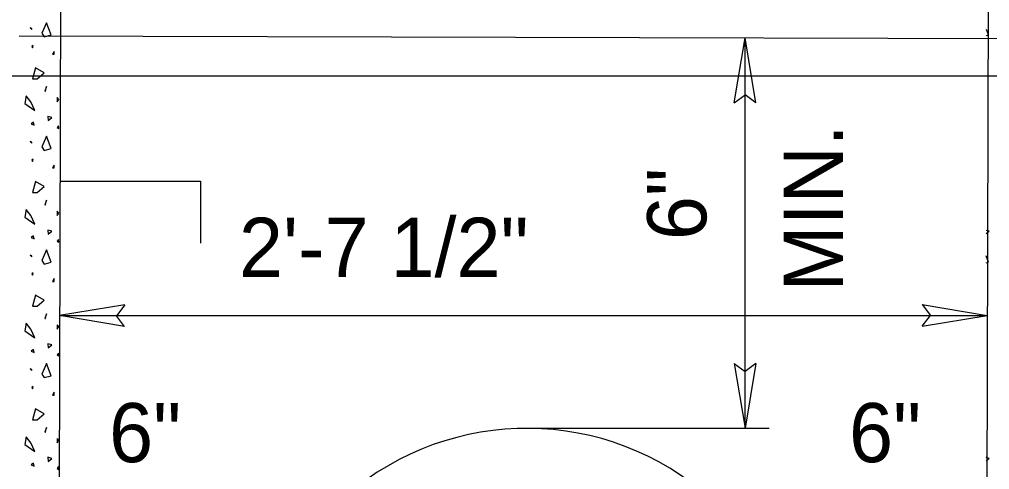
# Model space of a CAD drawing. Extents: x 9.6 to 16.8, y 2.2 to 12.2.
# Drawn here: x 14.996 to 15.979, y 7.746 to 8.202 of the extents above; entities that cross this region are included whole.
import ezdxf

# ---------------------------------------------------------------- set-up
doc = ezdxf.new("R2010")
doc.units = 0
for name, color, linetype in [('DETL-DIMS', 7, 'Continuous'), ('DETL-LINE', 7, 'Continuous'), ('DETL-NOTE', 7, 'Continuous'), ('DETL-PATT', 7, 'Continuous')]:
    doc.layers.add(name, color=color, linetype=linetype)

msp = doc.modelspace()

# ---------------------------------------------------------------- linework, layer by layer
at = {"layer": 'DETL-DIMS'}
for p, q in [((15.72059, 8.11769), (15.73157, 8.18357)), ((15.74255, 8.11769), (15.73157, 8.18357)), ((15.73157, 7.78769), (15.73157, 8.18357)), ((15.72059, 8.11769), (15.73157, 8.12592)), ((15.74255, 8.11769), (15.73157, 8.12592)), ((15.10275, 7.91282), (15.03682, 7.90196)), ((15.10275, 7.91282), (15.09447, 7.90184)), ((15.91118, 7.91306), (15.97702, 7.90196)), ((15.91118, 7.91306), (15.91937, 7.90208)), ((15.10267, 7.89086), (15.03682, 7.90196)), ((15.03682, 7.90196), (15.97702, 7.90196)), ((15.10267, 7.89086), (15.09447, 7.90184)), ((15.9111, 7.8911), (15.91937, 7.90208)), ((15.9111, 7.8911), (15.97702, 7.90196)), ((15.72059, 7.85357), (15.73157, 7.78769)), ((15.72059, 7.85357), (15.73157, 7.84533)), ((15.74255, 7.85357), (15.73157, 7.78769)), ((15.74255, 7.85357), (15.73157, 7.84533)), ((15.51027, 7.78769), (15.75604, 7.78769))]:
    msp.add_line(p, q, dxfattribs=at)
at = {"layer": 'DETL-LINE'}
for p, q in [((15.03902, 8.74647), (15.03486, 7.16059)), ((15.9791, 8.70102), (15.97506, 7.16059)), ((14.99573, 8.18549), (16.02733, 8.18278)), ((14.97361, 8.14518), (16.04459, 8.14518)), ((15.03804, 8.03835), (15.17957, 8.03835)), ((15.17957, 8.03835), (15.17957, 7.97545))]:
    msp.add_line(p, q, dxfattribs=at)
msp.add_arc((15.51033, 7.50778), 0.27991, 325.61931, 213.35871, dxfattribs=at)
at = {"layer": 'DETL-PATT'}
for points in [[(15.00871, 8.19298), (15.00698, 8.19357), (15.00871, 8.19184)], [(15.02125, 8.18467), (15.02831, 8.18651), (15.02353, 8.1989), (15.01886, 8.18831)], [(15.00996, 8.17576), (15.00871, 8.17463), (15.00941, 8.17337)], [(15.03129, 8.16984), (15.02957, 8.16686), (15.03129, 8.16686)], [(15.01404, 8.14188), (15.02125, 8.14796), (15.01235, 8.15318), (15.00941, 8.14188)], [(15.0218, 8.12945), (15.02239, 8.12945), (15.02353, 8.13427)], [(15.00275, 8.12467), (15.00165, 8.11702), (15.01165, 8.10984), (15.00757, 8.11875)], [(15.03424, 8.12298), (15.03424, 8.11875), (15.03608, 8.12114)], [(15.02478, 8.10392), (15.02533, 8.0998), (15.02886, 8.10278)], [(15.00812, 8.09627), (15.0111, 8.09502), (15.01051, 8.09796)], [(15.03424, 8.09263), (15.03608, 8.09149), (15.03553, 8.09443)], [(15.02125, 8.06945), (15.02831, 8.07129), (15.02353, 8.08373), (15.01886, 8.07314)], [(15.00871, 8.0778), (15.00698, 8.07835), (15.00871, 8.07667)], [(15.00996, 8.06055), (15.00871, 8.05945), (15.00941, 8.05816)], [(15.03129, 8.05463), (15.02957, 8.05169), (15.03129, 8.05169)], [(15.01404, 8.02667), (15.02125, 8.03275), (15.01235, 8.03796), (15.00941, 8.02667)], [(15.0218, 8.01427), (15.02239, 8.01427), (15.02353, 8.01906)], [(15.00275, 8.00945), (15.00165, 8.00184), (15.01165, 7.99463), (15.00757, 8.00353)], [(15.03424, 8.00776), (15.03424, 8.00353), (15.03608, 8.00592)], [(15.02478, 7.98871), (15.02533, 7.98463), (15.02886, 7.98757)], [(15.00812, 7.9811), (15.0111, 7.9798), (15.01051, 7.98278)], [(15.03424, 7.97741), (15.03608, 7.97627), (15.03553, 7.97925)], [(15.02125, 7.95427), (15.02831, 7.95608), (15.02353, 7.96851), (15.01886, 7.95792)], [(15.00871, 7.96259), (15.00698, 7.96314), (15.00871, 7.96145)], [(15.00996, 7.94537), (15.00871, 7.94424), (15.00941, 7.94298)], [(15.03129, 7.93945), (15.02957, 7.93647), (15.03129, 7.93647)], [(15.01404, 7.91149), (15.02125, 7.91757), (15.01235, 7.92278), (15.00941, 7.91149)], [(15.0218, 7.89906), (15.02239, 7.89906), (15.02353, 7.90384)], [(15.00275, 7.89427), (15.00165, 7.88663), (15.01165, 7.87945), (15.00757, 7.88831)], [(15.03424, 7.89255), (15.03424, 7.88831), (15.03608, 7.89075)], [(15.00812, 7.86588), (15.0111, 7.86463), (15.01051, 7.86757)], [(15.02478, 7.87349), (15.02533, 7.86941), (15.02886, 7.87239)], [(15.03424, 7.8622), (15.03608, 7.8611), (15.03553, 7.86404)], [(15.00871, 7.84737), (15.00698, 7.84796), (15.00871, 7.84627)], [(15.02125, 7.83906), (15.02831, 7.8409), (15.02353, 7.85333), (15.01886, 7.84275)], [(15.00996, 7.83016), (15.00871, 7.82902), (15.00941, 7.82776)], [(15.03129, 7.82424), (15.02957, 7.82125), (15.03129, 7.82125)], [(15.01404, 7.79627), (15.02125, 7.80235), (15.01235, 7.80757), (15.00941, 7.79627)], [(15.0218, 7.78384), (15.02239, 7.78384), (15.02353, 7.78867)], [(15.00275, 7.77906), (15.00165, 7.77145), (15.01165, 7.76424), (15.00757, 7.77314)], [(15.03424, 7.77737), (15.03424, 7.77314), (15.03608, 7.77553)], [(15.00812, 7.75067), (15.0111, 7.74941), (15.01051, 7.75239)], [(15.02478, 7.75831), (15.02533, 7.7542), (15.02886, 7.75718)]]:
    msp.add_lwpolyline(points, close=True, dxfattribs=at)
for points in [[(15.97627, 8.18596), (15.97843, 8.18651), (15.97627, 8.19212)], [(15.97604, 7.9851), (15.97898, 7.98757), (15.97604, 7.98839)], [(15.976, 7.95545), (15.97843, 7.95608), (15.976, 7.96239)], [(15.03604, 7.74608), (15.03553, 7.74886), (15.03424, 7.74702), (15.03604, 7.74592)], [(15.97576, 7.75447), (15.97898, 7.75718), (15.97576, 7.75808)]]:
    msp.add_lwpolyline(points, dxfattribs=at)

# ---------------------------------------------------------------- texts
at = {"layer": 'DETL-NOTE'}
for s, p in [('MIN.', (15.83075, 7.92655)), ('6"', (15.69231, 7.97851))]:
    msp.add_text(s, height=0.06, rotation=90, dxfattribs=at).set_placement(p)
for s, p in [('2\'-7 1/2"', (15.21859, 7.94118)), ('6"', (15.08698, 7.75333)), ('6"', (15.83694, 7.75333))]:
    msp.add_text(s, height=0.06, dxfattribs=at).set_placement(p)

doc.saveas('drawing.dxf')
